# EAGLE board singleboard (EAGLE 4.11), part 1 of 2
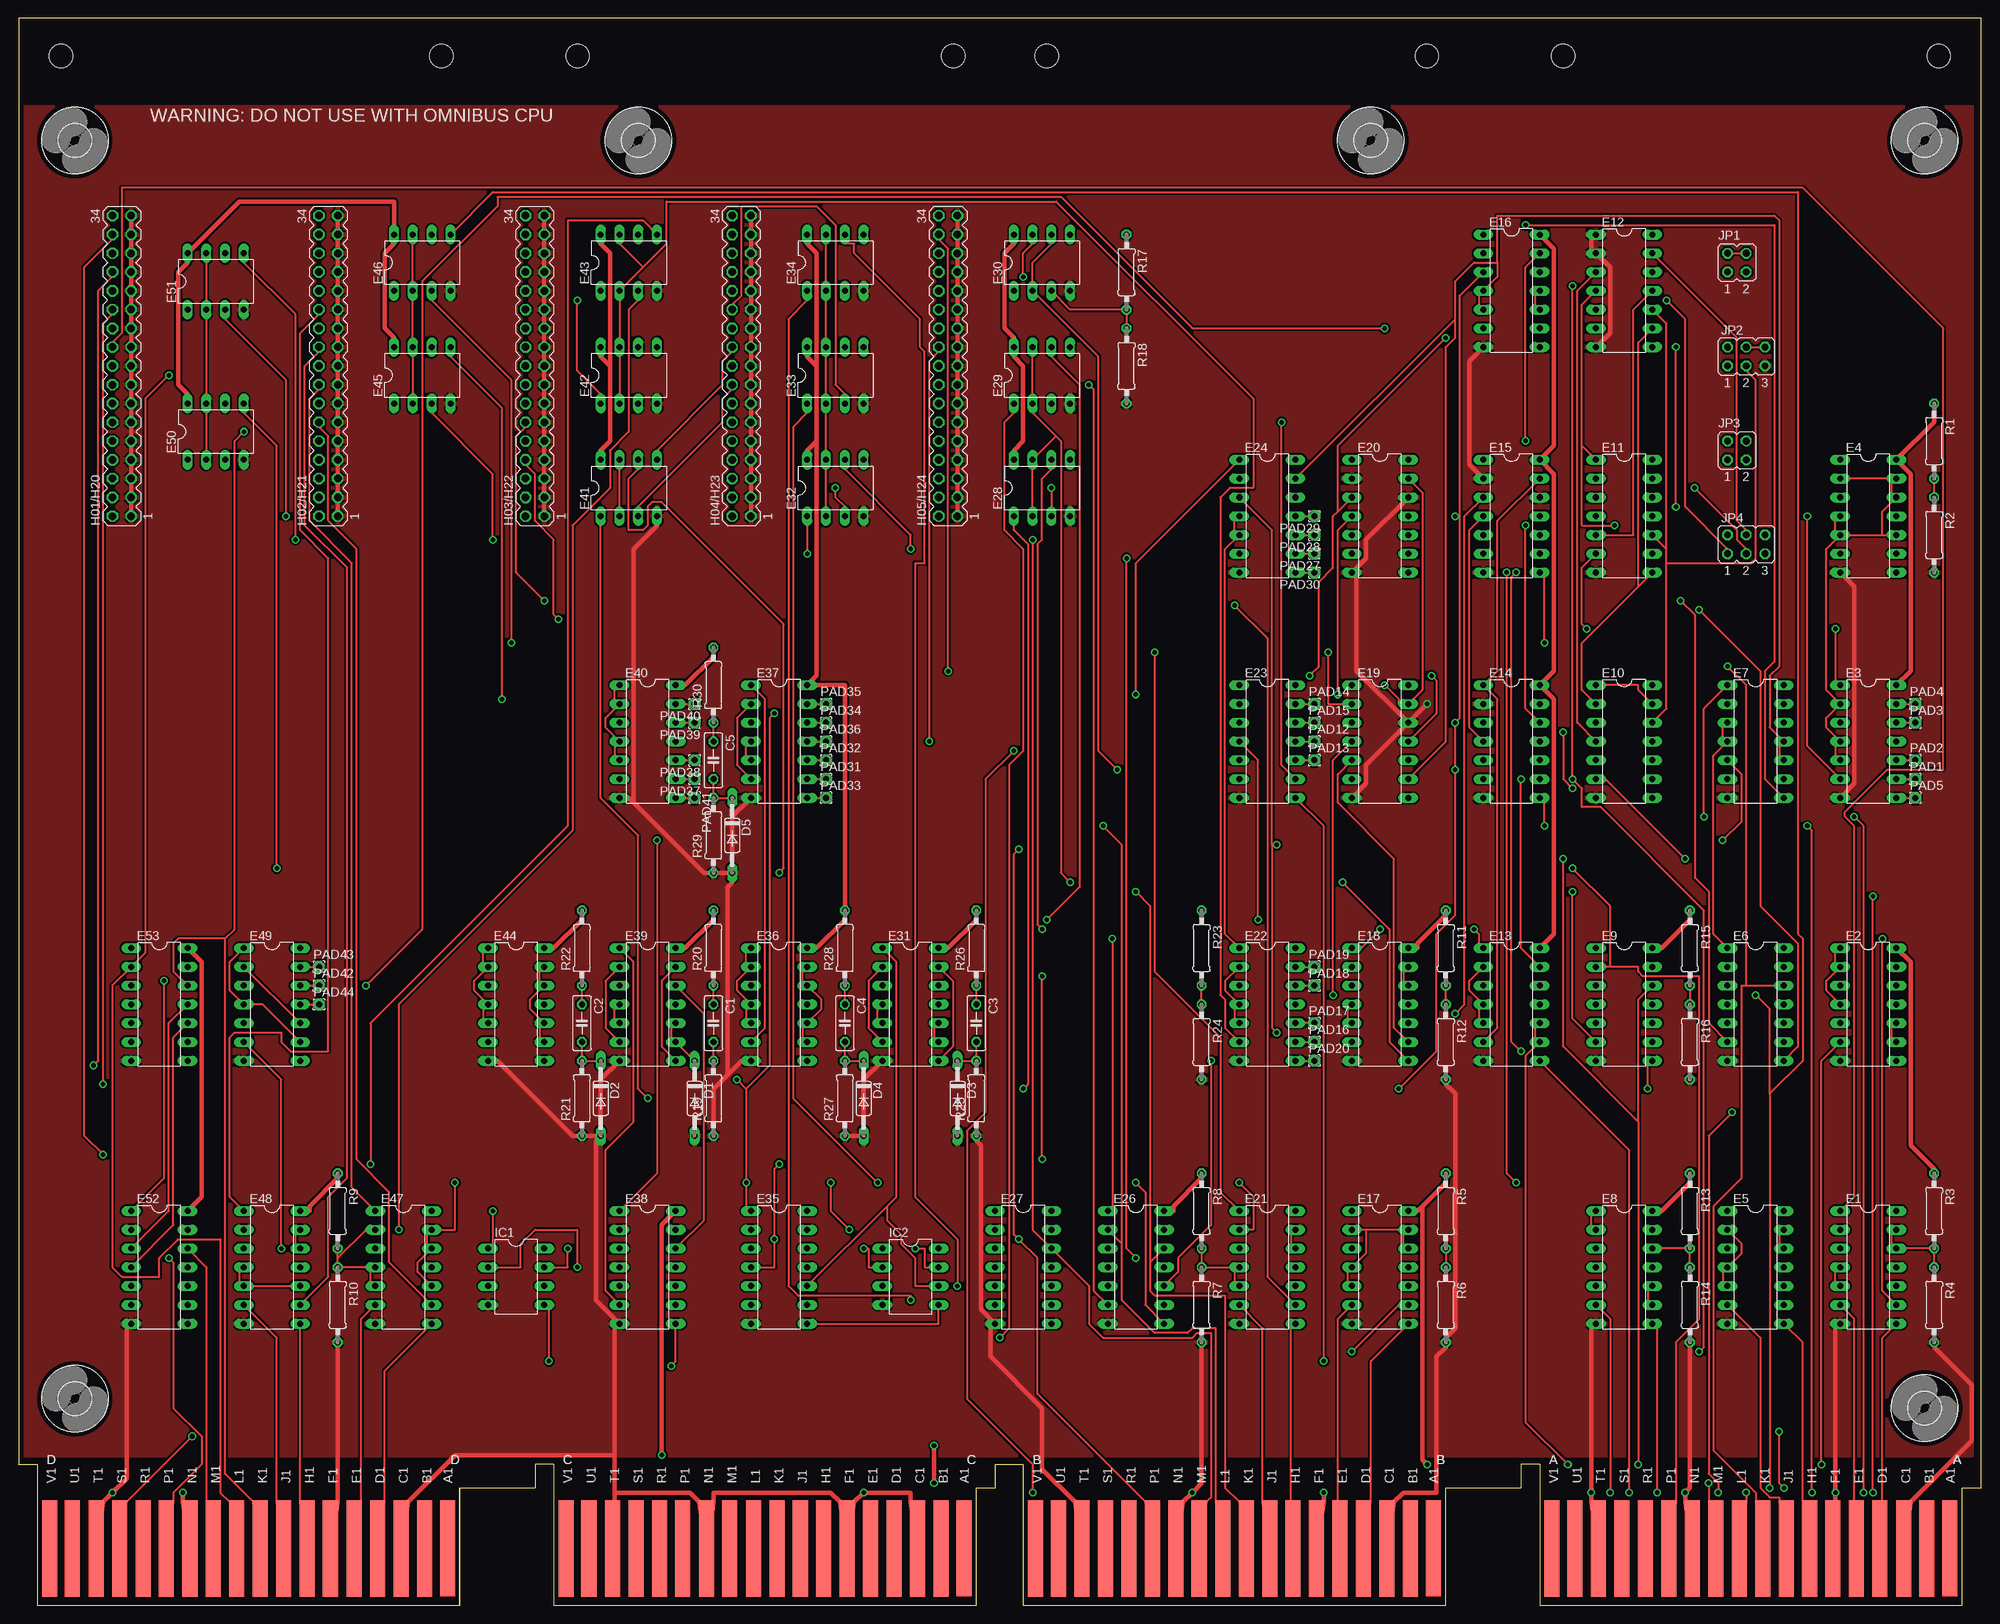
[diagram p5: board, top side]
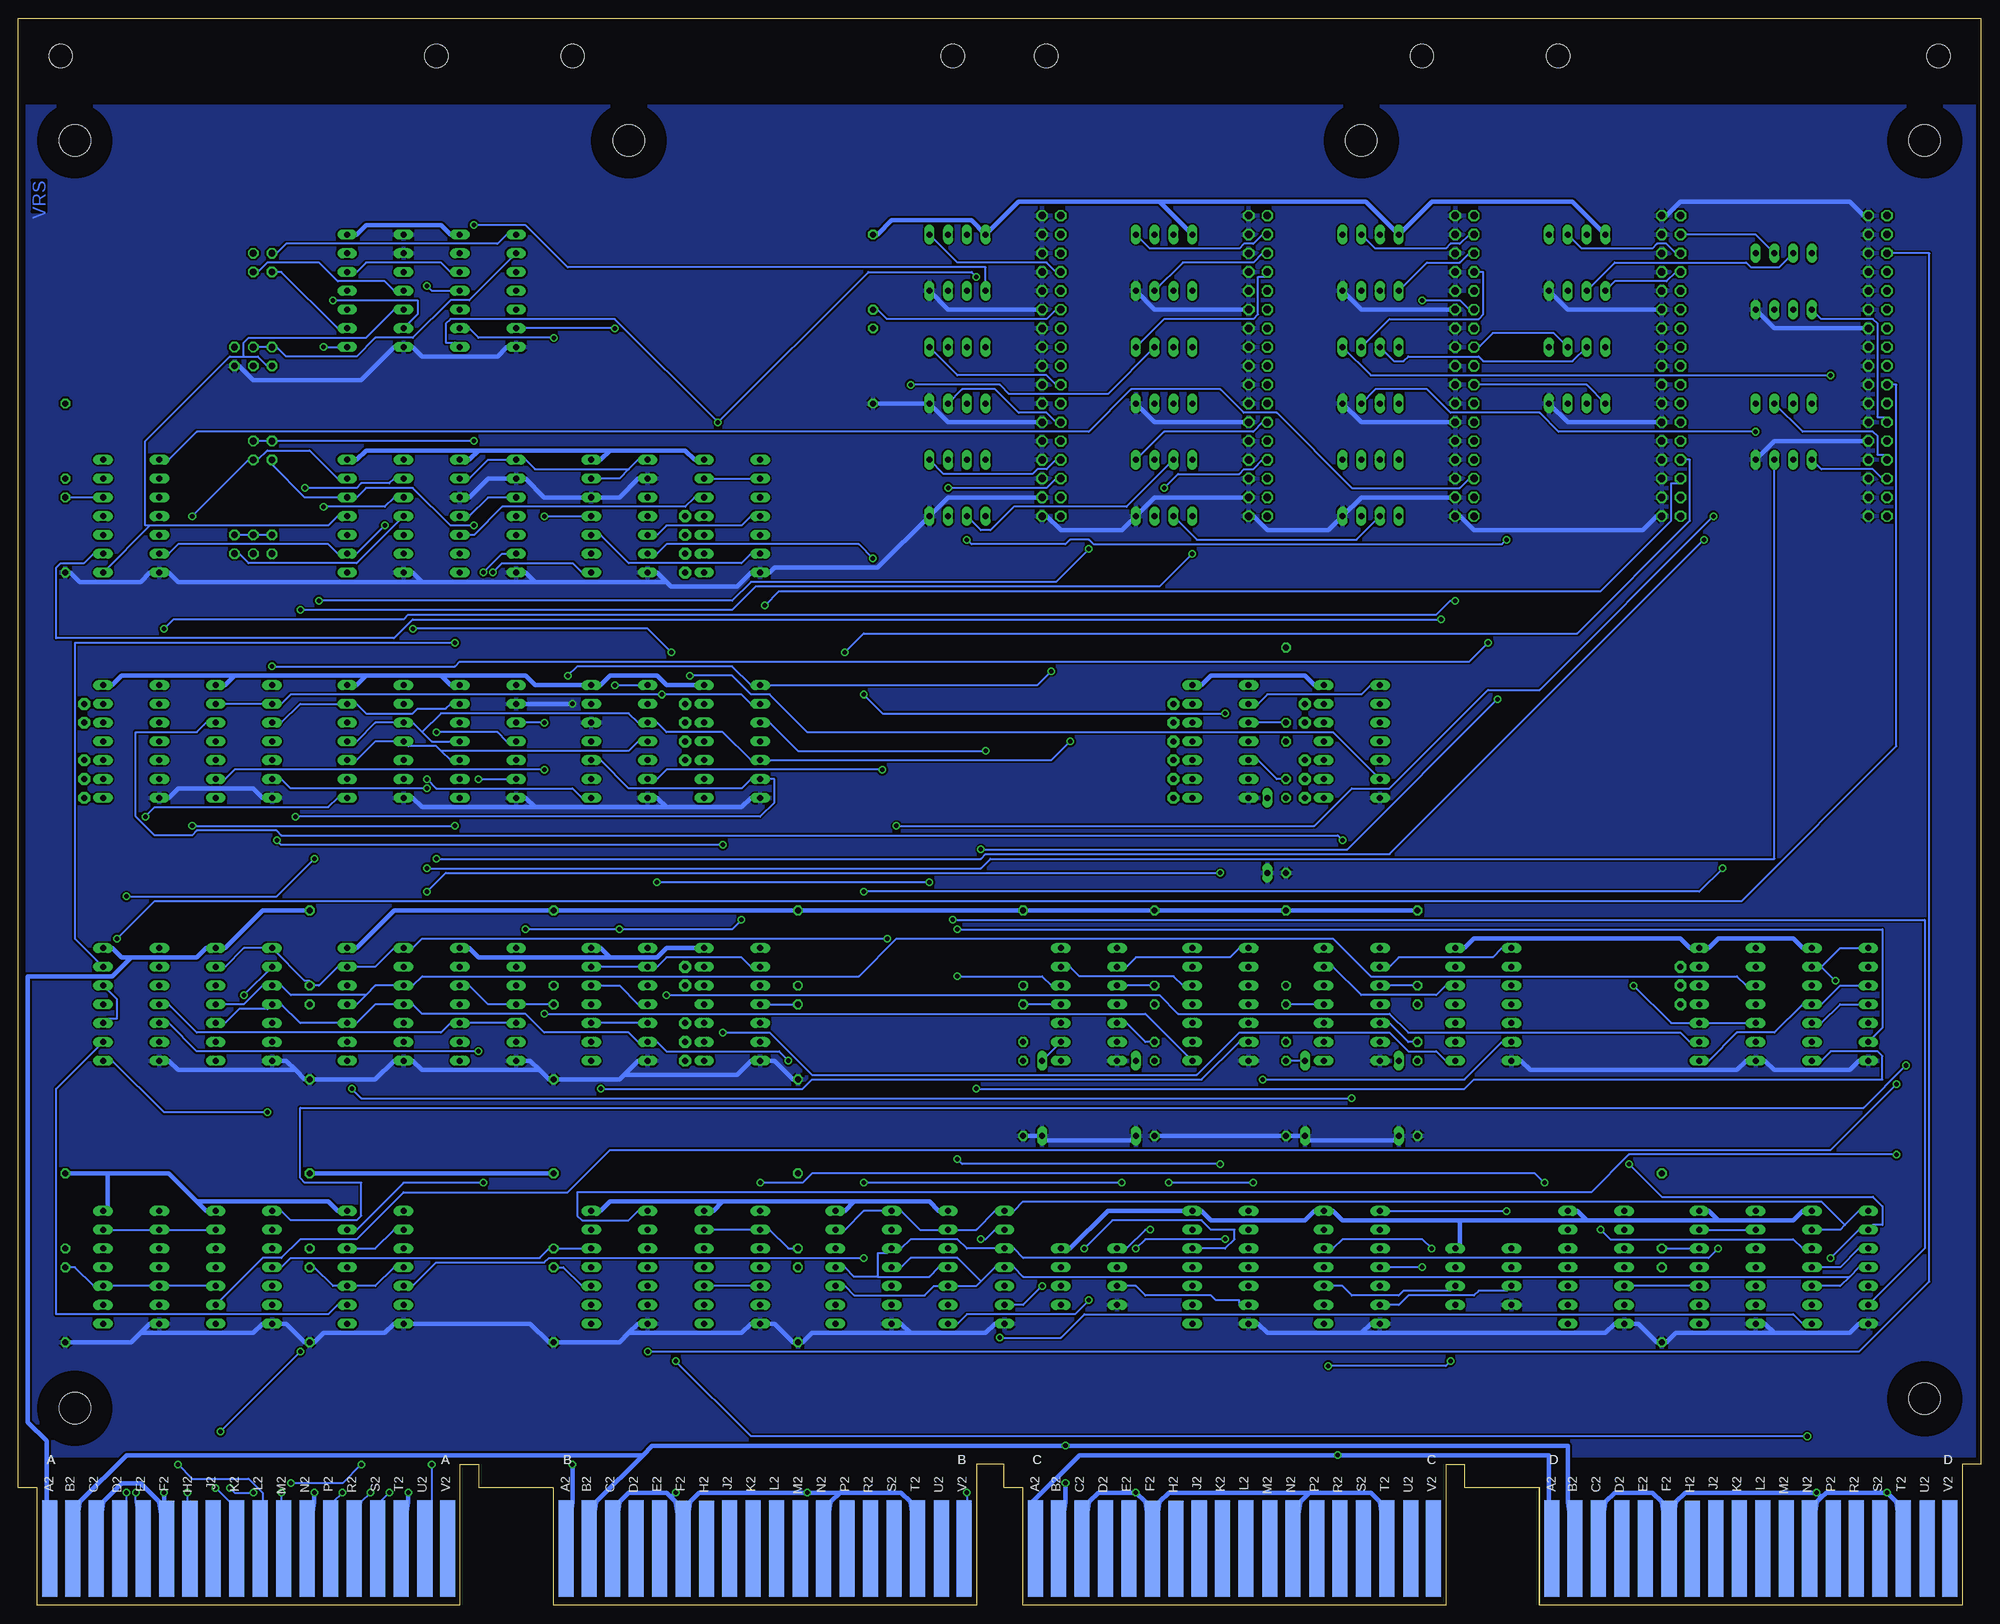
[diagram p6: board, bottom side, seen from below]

Size 265.43 x 214.63 mm. Coordinates in mm from the lower left corner, seen from the top.
Copper layers (1*16): Top 0.035mm / dielectric 1.5mm / Bottom 0.035mm
Design rules "olimex10mil": minimum track width 10mil, minimum drill 24mil, track to track 10mil, track to pad 10mil, pad to pad 10mil, via to via 10mil, smd to smd 10mil, copper to edge 25mil, drill to drill 10mil, minimum pad ring 10mil, minimum via ring 8mil, stop-mask expansion 0mil, vias tented up to drill 0mil, thermal gap 10mil
Net classes: 1 Power: width 0.635 mm
tRestrict: area 0,203.2 to 264.2,213.4
bRestrict: area 0,203.2 to 264.2,213.4

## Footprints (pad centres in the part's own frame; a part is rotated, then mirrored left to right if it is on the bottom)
C050-025X075 = drill 0.813 octagon: 1 -2.54,0; 2 2.54,0
DO35-10 = drill 0.813 long: A 5.08,0; C -5.08,0
DIL14 = drill 0.813 long: 1 -7.62,-3.81; 2 -5.08,-3.81; 3 -2.54,-3.81; 4 0,-3.81; 5 2.54,-3.81; 6 5.08,-3.81; 7 7.62,-3.81; 8 7.62,3.81; 9 5.08,3.81; 10 2.54,3.81; 11 0,3.81; 12 -2.54,3.81; 13 -5.08,3.81; 14 -7.62,3.81
DIL08 = drill 0.813 long: 1 -3.81,-3.81; 2 -1.27,-3.81; 3 1.27,-3.81; 4 3.81,-3.81; 5 3.81,3.81; 6 1.27,3.81; 7 -1.27,3.81; 8 -3.81,3.81
MA17-2 = drill 1.016 octagon: 1 -20.32,-1.27; 2 -20.32,1.27; 3 -17.78,-1.27; 4 -17.78,1.27; 5 -15.24,-1.27; 6 -15.24,1.27; 7 -12.7,-1.27; 8 -12.7,1.27; 9 -10.16,-1.27; 10 -10.16,1.27; 11 -7.62,-1.27; 12 -7.62,1.27; 13 -5.08,-1.27; 14 -5.08,1.27; 15 -2.54,-1.27; 16 -2.54,1.27; 17 0,-1.27; 18 0,1.27; 19 2.54,-1.27; 20 2.54,1.27; 21 5.08,-1.27; 22 5.08,1.27; 23 7.62,-1.27; 24 7.62,1.27; 25 10.16,-1.27; 26 10.16,1.27; 27 12.7,-1.27; 28 12.7,1.27; 29 15.24,-1.27; 30 15.24,1.27; 31 17.78,-1.27; 32 17.78,1.27; 33 20.32,-1.27; 34 20.32,1.27
JP2Q = drill 0.914 octagon: 1 -1.27,-1.27; 2 -1.27,1.27; 3 1.27,-1.27; 4 1.27,1.27
JP3Q = drill 0.914 octagon: 1 -2.54,-1.27; 2 -2.54,1.27; 3 0,-1.27; 4 0,1.27; 5 2.54,-1.27; 6 2.54,1.27
1,6/0,8 = drill 0.813 pad 1.6 octagon: 1 0,0
0207/10 = drill 0.813 octagon: 1 -5.08,0; 2 5.08,0
EDGE-CON8 = smd 2.032 x 13.017: AA1 261.223,7.709; AB1 258.118,7.684; AC1 254.956,7.684; AD1 251.765,7.684; AE1 248.59,7.693; AF1 245.389,7.668; AH1 242.24,7.668; AJ1 239.09,7.668; AK1 235.915,7.668; AL1 232.74,7.693; AM1 229.54,7.693; AN1 226.39,7.693; AP1 223.19,7.668; AR1 220.04,7.668; AS1 216.865,7.693; AT1 213.69,7.693; AU1 210.49,7.693; AV1 207.404,7.668; BA1 191.373,7.709; BB1 188.268,7.684; BC1 185.106,7.684; BD1 181.915,7.684; BE1 178.74,7.693; BF1 175.539,7.668; BH1 172.39,7.668; BJ1 169.24,7.668; BK1 166.065,7.668; BL1 162.89,7.693; BM1 159.69,7.693; BN1 156.54,7.693; BP1 153.34,7.668; BR1 150.19,7.668; BS1 147.015,7.693; BT1 143.84,7.693; BU1 140.64,7.693; BV1 137.554,7.668; CA1 127.873,7.709; CB1 124.768,7.684; CC1 121.606,7.684; CD1 118.415,7.684; CE1 115.24,7.693; CF1 112.039,7.668; CH1 108.89,7.668; CJ1 105.74,7.668; CK1 102.565,7.668; CL1 99.39,7.693; CM1 96.19,7.693; CN1 93.04,7.693; CP1 89.84,7.668; CR1 86.69,7.668; CS1 83.515,7.693; CT1 80.34,7.693; CU1 77.14,7.693; CV1 74.054,7.668; DA1 58.023,7.709; DB1 54.918,7.684; DC1 51.756,7.684; DD1 48.565,7.684; DE1 45.39,7.693; DF1 42.189,7.668; DH1 39.04,7.668; DJ1 35.89,7.668; DK1 32.715,7.668; DL1 29.54,7.693; DM1 26.34,7.693; DN1 23.19,7.693; DP1 19.99,7.668; DR1 16.84,7.668; DS1 13.665,7.693; DT1 10.49,7.693; DU1 7.29,7.693; DV1 4.204,7.668 | smd 2.032 x 13.017 bottom: AA2 261.223,7.69; AB2 258.102,7.668; AC2 254.94,7.668; AD2 251.765,7.693; AE2 248.59,7.693; AF2 245.389,7.642; AH2 242.24,7.642; AJ2 239.09,7.668; AK2 235.915,7.668; AL2 232.74,7.693; AM2 229.54,7.693; AN2 226.39,7.693; AP2 223.19,7.668; AR2 220.04,7.668; AS2 216.865,7.693; AT2 213.69,7.693; AU2 210.464,7.693; AV2 207.404,7.668; BA2 191.373,7.69; BB2 188.252,7.668; BC2 185.09,7.668; BD2 181.915,7.693; BE2 178.74,7.693; BF2 175.539,7.642; BH2 172.39,7.642; BJ2 169.24,7.668; BK2 166.065,7.668; BL2 162.89,7.693; BM2 159.69,7.693; BN2 156.54,7.693; BP2 153.34,7.668; BR2 150.19,7.668; BS2 147.015,7.693; BT2 143.84,7.693; BU2 140.614,7.693; BV2 137.554,7.668; CA2 127.873,7.69; CB2 124.752,7.668; CC2 121.59,7.668; CD2 118.415,7.693; CE2 115.24,7.693; CF2 112.039,7.642; CH2 108.89,7.642; CJ2 105.74,7.668; CK2 102.565,7.668; CL2 99.39,7.693; CM2 96.19,7.693; CN2 93.04,7.693; CP2 89.84,7.668; CR2 86.69,7.668; CS2 83.515,7.693; CT2 80.34,7.693; CU2 77.114,7.693; CV2 74.054,7.668; DA2 58.023,7.69; DB2 54.902,7.668; DC2 51.74,7.668; DD2 48.565,7.693; DE2 45.39,7.693; DF2 42.189,7.642; DH2 39.04,7.642; DJ2 35.89,7.668; DK2 32.715,7.668; DL2 29.54,7.693; DM2 26.34,7.693; DN2 23.19,7.693; DP2 19.99,7.668; DR2 16.84,7.668; DS2 13.665,7.693; DT2 10.49,7.693; DU2 7.264,7.693; DV2 4.204,7.668
OMNIBUS = hole 3.175: 208.915,209.55; 259.715,209.55; 190.5,209.55; 139.065,209.55; 75.616,209.55; 126.416,209.55; 57.201,209.55; 5.766,209.55
4,3 = hole 4.3: 0,0

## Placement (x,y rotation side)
C1  .22uf  [C050-025X075]  93.98,78.74 270 top
C2  .22uf  [C050-025X075]  76.2,78.74 270 top
C3  .22uf  [C050-025X075]  129.54,78.74 270 top
C4  .22uf  [C050-025X075]  111.76,78.74 270 top
C5  .22uf  [C050-025X075]  93.98,114.3 270 top
D1  1N4148  [DO35-10]  91.44,68.58 270 top
D2  1N4148  [DO35-10]  78.74,68.58 270 top
D3  1N4148  [DO35-10]  127,68.58 270 top
D4  1N4148  [DO35-10]  114.3,68.58 270 top
D5  1N4148  [DO35-10]  96.52,104.14 270 top
E1  74H40  [DIL14]  250.19,45.72 270 top
E2  74H40  [DIL14]  250.19,81.28 270 top
E3  74H40  [DIL14]  250.19,116.84 270 top
E4  74H40  [DIL14]  250.19,147.32 270 top
E5  74H40  [DIL14]  234.95,45.72 270 top
E6  74S74N  [DIL14]  234.95,81.28 270 top
E7  7410N  [DIL14]  234.95,116.84 270 top
E8  74H40  [DIL14]  217.17,45.72 270 top
E9  74S74N  [DIL14]  217.17,81.28 270 top
E10  74S74N  [DIL14]  217.17,116.84 270 top
E11  7404N  [DIL14]  217.17,147.32 270 top
E12  7400N  [DIL14]  217.17,177.8 270 top
E13  74H40  [DIL14]  201.93,81.28 270 top
E14  74S74N  [DIL14]  201.93,116.84 270 top
E15  74S74N  [DIL14]  201.93,147.32 270 top
E16  7410N  [DIL14]  201.93,177.8 270 top
E17  74H40  [DIL14]  184.15,45.72 270 top
E18  74H40  [DIL14]  184.15,81.28 270 top
E19  74S74N  [DIL14]  184.15,116.84 270 top
E20  74S74N  [DIL14]  184.15,147.32 270 top
E21  74H40  [DIL14]  168.91,45.72 270 top
E22  74H40  [DIL14]  168.91,81.28 270 top
E23  7404N  [DIL14]  168.91,116.84 270 top
E24  7410N  [DIL14]  168.91,147.32 270 top
E26  74S74N  [DIL14]  151.13,45.72 270 top
E27  74S74N  [DIL14]  135.89,45.72 270 top
E28  DS75453N  [DIL08]  138.43,151.13 0 top
E29  DS75453N  [DIL08]  138.43,166.37 0 top
E30  DS75453N  [DIL08]  138.43,181.61 0 top
E31  7400N  [DIL14]  120.65,81.28 270 top
E32  DS75453N  [DIL08]  110.49,151.13 0 top
E33  DS75453N  [DIL08]  110.49,166.37 0 top
E34  DS75453N  [DIL08]  110.49,181.61 0 top
E35  DS1005-250  [DIL14]  102.87,45.72 270 top
E36  74H40  [DIL14]  102.87,81.28 270 top
E37  7400N  [DIL14]  102.87,116.84 270 top
E38  DS1005-250  [DIL14]  85.09,45.72 270 top
E39  7400N  [DIL14]  85.09,81.28 270 top
E40  74H40  [DIL14]  85.09,116.84 270 top
E41  DS75453N  [DIL08]  82.55,151.13 0 top
E42  DS75453N  [DIL08]  82.55,166.37 0 top
E43  DS75453N  [DIL08]  82.55,181.61 0 top
E44  74H40  [DIL14]  67.31,81.28 270 top
E45  DS75453N  [DIL08]  54.61,166.37 0 top
E46  DS75453N  [DIL08]  54.61,181.61 0 top
E47  74H40  [DIL14]  52.07,45.72 270 top
E48  74H40  [DIL14]  34.29,45.72 270 top
E49  7400N  [DIL14]  34.29,81.28 270 top
E50  DS75453N  [DIL08]  26.67,158.75 0 top
E51  DS75453N  [DIL08]  26.67,179.07 0 top
E52  74S74N  [DIL14]  19.05,45.72 270 top
E53  74S74N  [DIL14]  19.05,81.28 270 top
H01/H20  [MA17-2]  13.97,167.64 90 top
H02/H21  [MA17-2]  41.91,167.64 90 top
H03/H22  [MA17-2]  69.85,167.64 90 top
H04/H23  [MA17-2]  97.79,167.64 90 top
H05/H24  [MA17-2]  125.73,167.64 90 top
IC1  DS1100M-250  [DIL08]  67.31,44.45 270 top
IC2  DS1100M-250  [DIL08]  120.65,44.45 270 top
JP1  [JP2Q]  232.41,181.61 0 top
JP2  [JP3Q]  233.68,168.91 0 top
JP3  [JP2Q]  232.41,156.21 0 top
JP4  [JP3Q]  233.68,143.51 0 top
PAD1  [1,6/0,8]  256.54,111.76 0 top
PAD2  [1,6/0,8]  256.54,114.3 0 top
PAD3  [1,6/0,8]  256.54,119.38 0 top
PAD4  [1,6/0,8]  256.54,121.92 0 top
PAD5  [1,6/0,8]  256.54,109.22 0 top
PAD12  [1,6/0,8]  175.26,116.84 0 top
PAD13  [1,6/0,8]  175.26,114.3 0 top
PAD14  [1,6/0,8]  175.26,121.92 0 top
PAD15  [1,6/0,8]  175.26,119.38 0 top
PAD16  [1,6/0,8]  175.26,76.2 0 top
PAD17  [1,6/0,8]  175.26,78.74 0 top
PAD18  [1,6/0,8]  175.26,83.82 0 top
PAD19  [1,6/0,8]  175.26,86.36 0 top
PAD20  [1,6/0,8]  175.26,73.66 0 top
PAD27  [1,6/0,8]  175.26,142.24 180 top
PAD28  [1,6/0,8]  175.26,144.78 180 top
PAD29  [1,6/0,8]  175.26,147.32 180 top
PAD30  [1,6/0,8]  175.26,139.7 180 top
PAD31  [1,6/0,8]  109.22,111.76 0 top
PAD32  [1,6/0,8]  109.22,114.3 0 top
PAD33  [1,6/0,8]  109.22,109.22 0 top
PAD34  [1,6/0,8]  109.22,119.38 0 top
PAD35  [1,6/0,8]  109.22,121.92 0 top
PAD36  [1,6/0,8]  109.22,116.84 0 top
PAD37  [1,6/0,8]  91.44,111.76 180 top
PAD38  [1,6/0,8]  91.44,114.3 180 top
PAD39  [1,6/0,8]  91.44,119.38 180 top
PAD40  [1,6/0,8]  91.44,121.92 180 top
PAD41  [1,6/0,8]  91.44,109.22 270 top
PAD42  [1,6/0,8]  40.64,83.82 0 top
PAD43  [1,6/0,8]  40.64,86.36 0 top
PAD44  [1,6/0,8]  40.64,81.28 0 top
R1  330  [0207/10]  259.08,157.48 270 top
R2  750  [0207/10]  259.08,144.78 270 top
R3  330  [0207/10]  259.08,53.34 270 top
R4  750  [0207/10]  259.08,40.64 270 top
R5  330  [0207/10]  193.04,53.34 270 top
R6  750  [0207/10]  193.04,40.64 270 top
R7  750  [0207/10]  160.02,40.64 270 top
R8  330  [0207/10]  160.02,53.34 270 top
R9  330  [0207/10]  43.18,53.34 270 top
R10  750  [0207/10]  43.18,40.64 270 top
R11  330  [0207/10]  193.04,88.9 270 top
R12  750  [0207/10]  193.04,76.2 270 top
R13  330  [0207/10]  226.06,53.34 270 top
R14  750  [0207/10]  226.06,40.64 270 top
R15  330  [0207/10]  226.06,88.9 270 top
R16  750  [0207/10]  226.06,76.2 270 top
R17  330  [0207/10]  149.86,180.34 270 top
R18  750  [0207/10]  149.86,167.64 270 top
R19  330  [0207/10]  93.98,68.58 90 top
R20  330  [0207/10]  93.98,88.9 90 top
R21  330  [0207/10]  76.2,68.58 90 top
R22  330  [0207/10]  76.2,88.9 90 top
R23  330  [0207/10]  160.02,88.9 270 top
R24  750  [0207/10]  160.02,76.2 270 top
R25  330  [0207/10]  129.54,68.58 90 top
R26  330  [0207/10]  129.54,88.9 90 top
R27  330  [0207/10]  111.76,68.58 90 top
R28  330  [0207/10]  111.76,88.9 90 top
R29  330  [0207/10]  93.98,104.14 90 top
R30  330  [0207/10]  93.98,124.46 90 top
U$1  [EDGE-CON8]  0,0 0 top
U$2  OUTLINE-OMNIBUS  [OMNIBUS]  0,0 0 top
U$20  [4,3]  257.81,198.12 270 top
U$66  [4,3]  83.82,198.12 270 top
U$67  [4,3]  182.88,198.12 270 top
U$82  [4,3]  257.81,26.67 270 top
U$83  [4,3]  7.62,27.94 270 top
U$86  [4,3]  7.62,198.12 270 top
